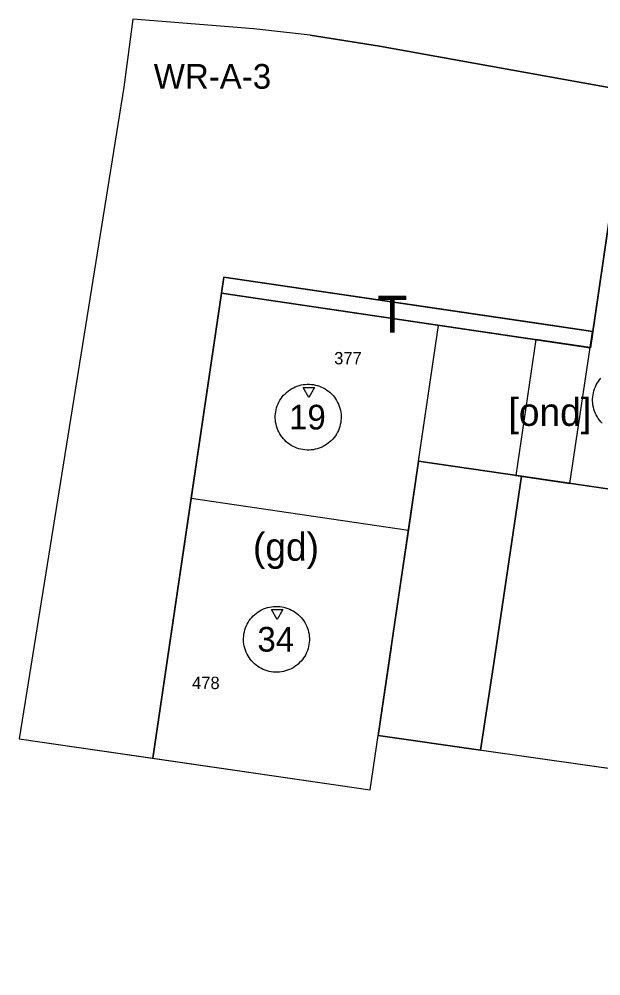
# Model space of a CAD drawing. Extents: x 104705 to 105186, y 424858 to 425816.
# Drawn here: x 104852.1 to 104905.1, y 425000.2 to 425087.4 of the extents above; entities that cross this region are included whole.
import ezdxf

# ---------------------------------------------------------------- set-up
doc = ezdxf.new("R2010")
doc.units = 0
for name, color, linetype in [('BP_ALG_bestemminggrens', 7, 'Continuous'), ('BP_BA_onderdoorgang', 7, 'Continuous'), ('BP_BPG_Plangebied', 7, 'Continuous'), ('BP_BV_Bouwvlak', 7, 'Continuous'), ('BP_DB_Waarde - Archeologie - 3', 7, 'Continuous'), ('BP_EB_Groen', 7, 'Continuous'), ('BP_EB_Tuin', 7, 'Continuous'), ('BP_EB_Verkeer', 7, 'Continuous'), ('BP_EB_Wonen', 7, 'Continuous'), ('BP_FA_gemengd', 7, 'Continuous'), ('BP_MV_maatvoering', 7, 'Continuous'), ('BP_TXT_tekst', 7, 'Continuous'), ('Default', 7, 'Continuous')]:
    doc.layers.add(name, color=color, linetype=linetype)

msp = doc.modelspace()

# ---------------------------------------------------------------- linework, layer by layer
at = {"layer": 'BP_ALG_bestemminggrens'}
for p, q in [((104904.141, 425057.488), (104906.778, 425075.366)), ((104864.283, 425020.039), (104870.537, 425062.444)), ((104870.537, 425062.444), (104904.141, 425057.488)), ((104885.988, 425030.133), (104884.802, 425022.147))]:
    msp.add_line(p, q, dxfattribs=at)
for points in [[(104904.365, 425058.967), (104899.91, 425059.628), (104870.755, 425063.928), (104870.537, 425062.444)], [(104894.145, 425020.819), (104895.344, 425028.689), (104897.865, 425045.778), (104914.194, 425043.37), (104914.903, 425048.497)]]:
    msp.add_lwpolyline(points, dxfattribs=at)
at = {"layer": 'BP_BA_onderdoorgang'}
msp.add_lwpolyline([(104897.34, 425045.856), (104902.286, 425045.126), (104904.113, 425057.51), (104899.166, 425058.24)], close=True, dxfattribs=at)
at = {"layer": 'BP_BPG_Plangebied'}
for p, q in [((104861.646, 425081.225), (104852.112, 425021.836)), ((104852.112, 425021.836), (104852.112, 425021.836)), ((104852.112, 425021.836), (104884.082, 425017.207))]:
    msp.add_line(p, q, dxfattribs=at)
for points in [[(104878.613, 425085.968), (104873.502, 425086.542), (104862.473, 425087.43), (104861.646, 425081.225)], [(104878.613, 425085.968), (104884.922, 425084.964), (104929.095, 425077.019), (104992.295, 425065.592), (105021.483, 425060.269), (105072.728, 425051.043), (105083.131, 425049.138)], [(104884.082, 425017.207), (104884.802, 425022.147), (104950.686, 425012.785), (104949.318, 425003.038)]]:
    msp.add_lwpolyline(points, dxfattribs=at)
at = {"layer": 'BP_BV_Bouwvlak'}
for p, q in [((104904.141, 425057.488), (104906.559, 425073.882)), ((104864.283, 425020.039), (104870.537, 425062.444)), ((104870.537, 425062.444), (104904.141, 425057.488)), ((104888.499, 425047.16), (104884.802, 425022.147)), ((104914.194, 425043.37), (104888.499, 425047.16))]:
    msp.add_line(p, q, dxfattribs=at)
at = {"layer": 'BP_DB_Waarde - Archeologie - 3'}
for p, q in [((104861.646, 425081.225), (104852.112, 425021.836)), ((104852.112, 425021.836), (104884.082, 425017.207))]:
    msp.add_line(p, q, dxfattribs=at)
for points in [[(104878.613, 425085.968), (104873.502, 425086.542), (104862.473, 425087.43), (104861.646, 425081.225)], [(105083.131, 425049.138), (105072.728, 425051.043), (105021.483, 425060.269), (104992.295, 425065.592), (104929.095, 425077.019), (104884.922, 425084.964), (104878.613, 425085.968)], [(104884.082, 425017.207), (104884.802, 425022.147), (104950.686, 425012.785), (104952.424, 425012.852), (104950.686, 425012.785), (104949.318, 425003.038), (104964.917, 425000.694), (104965.27, 425002.967), (104982.501, 425000.245)]]:
    msp.add_lwpolyline(points, dxfattribs=at)
at = {"layer": 'BP_EB_Groen'}
for p, q in [((104885.988, 425030.133), (104884.802, 425022.147)), ((104884.802, 425022.147), (104950.686, 425012.785))]:
    msp.add_line(p, q, dxfattribs=at)
msp.add_lwpolyline([(104961.536, 425018.477), (104964.78, 425039.501), (104914.903, 425048.497), (104914.148, 425043.377), (104897.865, 425045.778), (104895.354, 425028.752), (104894.145, 425020.819), (104884.802, 425022.147), (104885.988, 425030.133)], dxfattribs=at)
at = {"layer": 'BP_EB_Tuin'}
msp.add_line((104870.539, 425062.461), (104904.113, 425057.51), dxfattribs=at)
msp.add_lwpolyline([(104904.113, 425057.51), (104904.329, 425058.977), (104870.755, 425063.928), (104870.539, 425062.461)], dxfattribs=at)
at = {"layer": 'BP_EB_Verkeer'}
for p, q in [((104861.646, 425081.225), (104852.112, 425021.836)), ((104867.784, 425043.779), (104870.537, 425062.444)), ((104904.365, 425058.967), (104904.364, 425058.96)), ((104864.288, 425020.073), (104867.784, 425043.779)), ((104852.112, 425021.836), (104864.288, 425020.073))]:
    msp.add_line(p, q, dxfattribs=at)
for points in [[(104878.613, 425085.968), (104873.502, 425086.542), (104862.473, 425087.43), (104861.646, 425081.225)], [(105083.131, 425049.138), (105072.728, 425051.043), (105021.483, 425060.269), (104992.295, 425065.592), (104929.095, 425077.019), (104884.922, 425084.964), (104878.613, 425085.968)], [(104904.364, 425058.96), (104904.357, 425058.961), (104906.705, 425074.871)], [(104870.537, 425062.444), (104870.755, 425063.928), (104904.365, 425058.967)]]:
    msp.add_lwpolyline(points, dxfattribs=at)
at = {"layer": 'BP_EB_Wonen'}
for p, q in [((104906.559, 425073.882), (104904.141, 425057.488)), ((104870.537, 425062.444), (104864.288, 425020.073)), ((104888.499, 425047.16), (104887.568, 425040.861)), ((104887.568, 425040.861), (104888.499, 425047.16)), ((104897.865, 425045.778), (104888.499, 425047.16)), ((104888.499, 425047.16), (104897.865, 425045.778)), ((104887.568, 425040.861), (104885.982, 425030.134)), ((104885.988, 425030.133), (104887.568, 425040.861)), ((104887.57, 425040.861), (104887.568, 425040.861)), ((104884.802, 425022.147), (104885.988, 425030.133)), ((104884.082, 425017.207), (104884.802, 425022.147)), ((104864.288, 425020.073), (104884.082, 425017.207))]:
    msp.add_line(p, q, dxfattribs=at)
for points in [[(104904.141, 425057.488), (104899.691, 425058.144), (104870.537, 425062.444)], [(104897.865, 425045.778), (104914.194, 425043.37), (104914.903, 425048.497)], [(104885.988, 425030.133), (104884.802, 425022.147), (104894.145, 425020.819), (104895.354, 425028.752), (104897.865, 425045.778)], [(104887.568, 425040.861), (104887.57, 425040.861)], [(104885.982, 425030.134), (104885.988, 425030.133)]]:
    msp.add_lwpolyline(points, dxfattribs=at)
at = {"layer": 'BP_FA_gemengd'}
msp.add_lwpolyline([(104864.288, 425020.073), (104884.082, 425017.207), (104890.323, 425059.526), (104870.537, 425062.444)], close=True, dxfattribs=at)
at = {"layer": 'BP_MV_maatvoering'}
for p, q in [((104888.499, 425047.16), (104890.323, 425059.526)), ((104867.784, 425043.779), (104887.57, 425040.861))]:
    msp.add_line(p, q, dxfattribs=at)
msp.add_lwpolyline([(104905.213, 425050.608), (104905.084, 425050.746), (104904.964, 425050.891), (104904.855, 425051.044), (104904.754, 425051.205), (104904.664, 425051.37), (104904.585, 425051.541), (104904.517, 425051.716), (104904.46, 425051.896), (104904.414, 425052.079), (104904.379, 425052.264), (104904.357, 425052.451), (104904.346, 425052.639), (104904.346, 425052.828), (104904.36, 425053.015), (104904.384, 425053.203), (104904.42, 425053.387), (104904.468, 425053.57), (104904.528, 425053.749), (104904.598, 425053.924), (104904.679, 425054.094), (104904.771, 425054.259), (104904.873, 425054.418), (104904.984, 425054.569), (104905.105, 425054.713)], dxfattribs=at)
for points in [[(104881.107, 425049.785), (104881.015, 425049.62), (104880.913, 425049.461), (104880.802, 425049.31), (104880.681, 425049.166), (104880.552, 425049.029), (104880.414, 425048.9), (104880.268, 425048.78), (104880.115, 425048.671), (104879.955, 425048.57), (104879.79, 425048.48), (104879.619, 425048.401), (104879.443, 425048.333), (104879.263, 425048.276), (104879.08, 425048.23), (104878.896, 425048.195), (104878.708, 425048.173), (104878.521, 425048.162), (104878.332, 425048.162), (104878.144, 425048.176), (104877.957, 425048.2), (104877.772, 425048.236), (104877.589, 425048.284), (104877.411, 425048.344), (104877.235, 425048.414), (104877.066, 425048.495), (104876.901, 425048.587), (104876.742, 425048.689), (104876.59, 425048.8), (104876.446, 425048.921), (104876.31, 425049.05), (104876.181, 425049.188), (104876.061, 425049.334), (104875.951, 425049.487), (104875.851, 425049.647), (104875.761, 425049.812), (104875.681, 425049.983), (104875.614, 425050.159), (104875.557, 425050.339), (104875.51, 425050.522), (104875.476, 425050.706), (104875.453, 425050.894), (104875.443, 425051.081), (104875.443, 425051.27), (104875.456, 425051.458), (104875.48, 425051.645), (104875.516, 425051.83), (104875.564, 425052.013), (104875.624, 425052.191), (104875.695, 425052.367), (104875.776, 425052.536), (104875.867, 425052.701), (104875.969, 425052.86), (104876.08, 425053.012), (104876.202, 425053.156), (104876.331, 425053.292), (104876.469, 425053.421), (104876.614, 425053.541), (104876.767, 425053.651), (104876.928, 425053.751), (104877.093, 425053.841), (104877.264, 425053.921), (104877.439, 425053.988), (104877.619, 425054.045), (104877.802, 425054.092), (104877.987, 425054.126), (104878.174, 425054.149), (104878.362, 425054.159), (104878.551, 425054.159), (104878.738, 425054.146), (104878.926, 425054.122), (104879.11, 425054.086), (104879.293, 425054.038), (104879.472, 425053.978), (104879.647, 425053.907), (104879.817, 425053.826), (104879.982, 425053.735), (104880.141, 425053.633), (104880.292, 425053.522), (104880.436, 425053.4), (104880.573, 425053.271), (104880.702, 425053.133), (104880.822, 425052.988), (104880.931, 425052.835), (104881.032, 425052.674), (104881.122, 425052.509), (104881.201, 425052.338), (104881.269, 425052.163), (104881.326, 425051.983), (104881.372, 425051.8), (104881.407, 425051.615), (104881.429, 425051.428), (104881.44, 425051.24), (104881.44, 425051.051), (104881.426, 425050.864), (104881.402, 425050.676), (104881.366, 425050.492), (104881.318, 425050.309), (104881.258, 425050.13), (104881.188, 425049.955)], [(104878.51, 425052.964), (104877.988, 425053.861), (104879.028, 425053.865)], [(104878.216, 425029.543), (104878.125, 425029.378), (104878.023, 425029.219), (104877.912, 425029.068), (104877.79, 425028.924), (104877.661, 425028.787), (104877.523, 425028.658), (104877.378, 425028.538), (104877.225, 425028.429), (104877.064, 425028.328), (104876.899, 425028.238), (104876.728, 425028.159), (104876.553, 425028.091), (104876.373, 425028.034), (104876.19, 425027.988), (104876.005, 425027.953), (104875.818, 425027.931), (104875.63, 425027.92), (104875.441, 425027.92), (104875.254, 425027.934), (104875.066, 425027.958), (104874.882, 425027.994), (104874.699, 425028.042), (104874.52, 425028.102), (104874.345, 425028.172), (104874.175, 425028.253), (104874.01, 425028.345), (104873.851, 425028.447), (104873.7, 425028.558), (104873.556, 425028.679), (104873.419, 425028.808), (104873.29, 425028.946), (104873.17, 425029.092), (104873.061, 425029.245), (104872.96, 425029.405), (104872.87, 425029.57), (104872.791, 425029.741), (104872.723, 425029.917), (104872.666, 425030.097), (104872.62, 425030.28), (104872.585, 425030.464), (104872.563, 425030.652), (104872.552, 425030.839), (104872.552, 425031.028), (104872.566, 425031.216), (104872.59, 425031.403), (104872.626, 425031.588), (104872.674, 425031.771), (104872.734, 425031.949), (104872.804, 425032.125), (104872.885, 425032.294), (104872.977, 425032.459), (104873.079, 425032.618), (104873.19, 425032.77), (104873.311, 425032.914), (104873.44, 425033.05), (104873.578, 425033.179), (104873.724, 425033.299), (104873.877, 425033.409), (104874.037, 425033.509), (104874.202, 425033.599), (104874.373, 425033.679), (104874.549, 425033.746), (104874.729, 425033.803), (104874.912, 425033.85), (104875.096, 425033.884), (104875.284, 425033.907), (104875.471, 425033.917), (104875.66, 425033.917), (104875.848, 425033.904), (104876.035, 425033.88), (104876.22, 425033.844), (104876.403, 425033.796), (104876.581, 425033.736), (104876.757, 425033.665), (104876.926, 425033.584), (104877.091, 425033.493), (104877.25, 425033.391), (104877.402, 425033.28), (104877.546, 425033.158), (104877.682, 425033.029), (104877.811, 425032.891), (104877.931, 425032.746), (104878.041, 425032.593), (104878.141, 425032.432), (104878.231, 425032.267), (104878.311, 425032.096), (104878.378, 425031.921), (104878.435, 425031.741), (104878.482, 425031.558), (104878.516, 425031.373), (104878.539, 425031.186), (104878.549, 425030.998), (104878.549, 425030.809), (104878.536, 425030.622), (104878.512, 425030.434), (104878.476, 425030.25), (104878.428, 425030.067), (104878.368, 425029.888), (104878.297, 425029.713)], [(104875.62, 425032.722), (104875.098, 425033.619), (104876.137, 425033.623)]]:
    msp.add_lwpolyline(points, close=True, dxfattribs=at)

# ---------------------------------------------------------------- texts
for s, p in [('19', (104876.696, 425050.036)), ('34', (104873.813, 425029.794))]:
    msp.add_text(s, height=2.25, dxfattribs=at).set_placement(p)
at = {"layer": 'BP_TXT_tekst'}
for s, height, p in [('WR-A-3', 2.25, (104864.37, 425081.089)), ('T', 3.375, (104884.725, 425058.846)), ('[ond]', 2.5312, (104896.686, 425050.366)), ('(gd)', 2.5312, (104873.408, 425038.078))]:
    msp.add_text(s, height=height, dxfattribs=at).set_placement(p)
at = {"layer": 'Default'}
for s, p in [('377', (104880.81, 425055.972)), ('478', (104867.865, 425026.381))]:
    msp.add_text(s, height=1.125, dxfattribs=at).set_placement(p)

doc.saveas('drawing.dxf')
